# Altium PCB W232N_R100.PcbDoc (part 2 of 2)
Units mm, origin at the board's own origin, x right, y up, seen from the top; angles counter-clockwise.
Board outline 70 x 46.25 mm, 4 copper layers (Top Layer, Layer 1, Layer 2, Bottom Layer), stack 1.584 mm thick; 133 components, 105 nets, 435 pads, 346 vias.
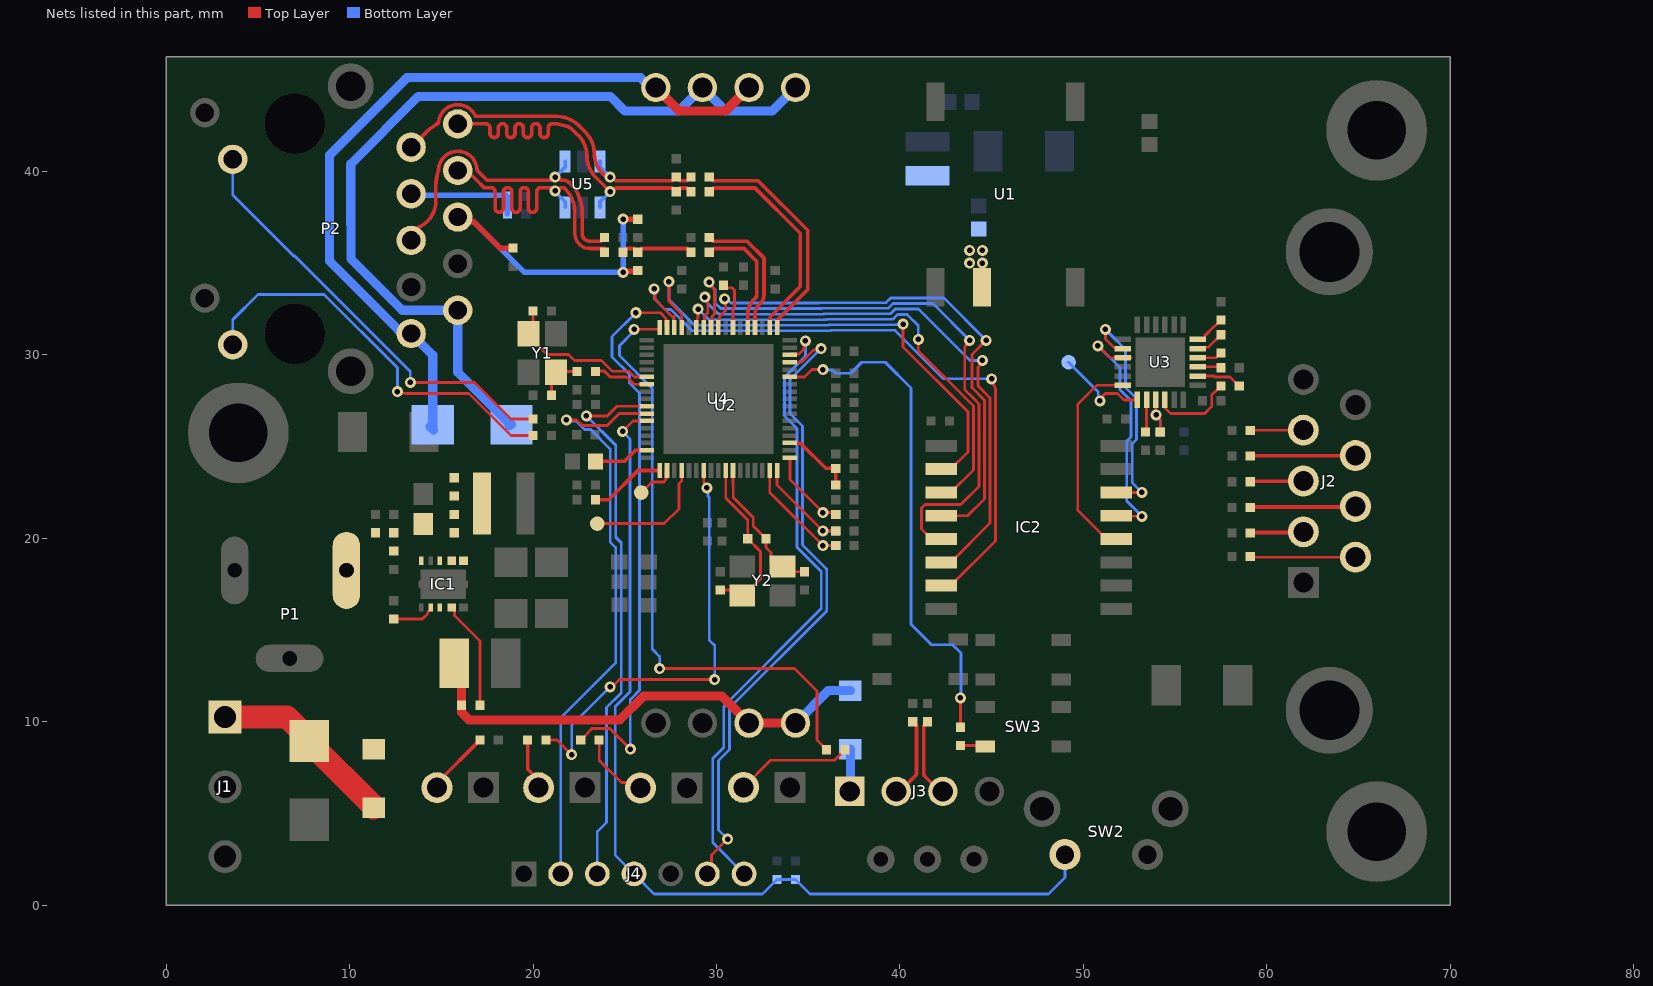
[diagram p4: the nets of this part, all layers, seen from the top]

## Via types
v1: diameter 0.6, hole 0.3, Top Layer to Bottom Layer, tented both sides, 346 vias

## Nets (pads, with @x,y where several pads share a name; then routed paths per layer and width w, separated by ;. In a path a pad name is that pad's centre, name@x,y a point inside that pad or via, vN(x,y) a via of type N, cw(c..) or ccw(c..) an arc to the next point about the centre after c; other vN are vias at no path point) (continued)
MDI_R1_P: C20.1 R34.2 R37.2 | length 4
  Top Layer w0.2: C20.1@24.9,35.6 25.1,35.8 25.5,35.8 R37.2@25.7,35.6 25.9,35.8 28.4,35.8 R34.2@28.6,35.6
MDI_R_N: C23.2 P2.R6 U5.4 | length 18.7
  Top Layer w0.2: P2.R6@13.35,36.247 13.35,36.69 cw(c13.55,36.689) 13.504,36.883 ccw(c13.151,38.388) 14.696,38.388 14.696,39.181 cw(c17.412,39.19) 14.831,40.034 ccw(c14.641,40.096) 14.84,40.089 cw(c15.89,40.057) 16.937,40.142 ccw(c17.136,40.16) 16.993,40.02 17.09,39.923 17.488,39.525 20.917,39.525 21.092,39.7 v1(21.2,39.7) cw(c21.2,39.439) 21.385,39.623 ccw(c21.622,39.861) 21.622,39.525 cw(c21.622,38.979) 22.008,39.365 22.039,39.334 ; 22.039,39.334 cw(c20.506,37.802) 22.674,37.802 22.674,36.626 ccw(c23.1,36.626) 23.1,36.2 23.7,36.2 C23.2@23.9,36.4
  Bottom Layer w0.2: v1(21.2,39.7) 21.75,40.25 U5.4@21.75,40.55
MDI_R_P: C20.2 P2.R3 U5.3 | length 18.8
  Top Layer w0.2: P2.R3@16.218,40.23 16.918,39.53 17.323,39.125 17.699,39.125 cw(c17.699,38.898) 17.926,38.898 17.926,38.005 ccw(c18.153,38.005) 18.38,38.005 18.38,38.898 cw(c18.607,38.898) 18.834,38.898 18.834,38.005 ccw(c19.061,38.005) 19.288,38.005 19.288,38.898 cw(c19.515,38.898) 19.742,38.898 19.742,38.005 ccw(c19.969,38.005) 20.196,38.005 20.196,38.898 cw(c20.423,38.898) 20.423,39.125 20.917,39.125 21.092,38.95 21.1,38.95 v1(21.2,38.95) ccw(c21.2,39.211) 21.385,39.027 21.413,39.054 cw(c21.583,38.884) 21.583,39.125 cw(c21.583,38.884) 21.753,39.054 cw(c20.497,37.798) 22.274,37.798 22.274,36.626 ccw(c23.1,36.626) 22.274,36.607 ccw(c23.1,36.626) 23.081,35.8 ccw(c23.1,36.626) 23.1,35.8 C20.2@23.866,35.8
  Bottom Layer w0.2: v1(21.2,38.95) 21.2,38.9 21.75,38.35 U5.3@21.75,38.05
MDI_T_N: P2.R2 R27.1 R31.2 U5.6 | length 20.6
  Top Layer w0.2: P2.R2@13.35,41.327 14.179,42.156 cw(c15.975,40.36) 14.748,42.584 ccw(c14.65,42.759) 14.849,42.732 cw(c15.89,42.597) 15.147,43.339 ; 15.148,43.34 cw(c15.89,42.597) 15.89,43.647 cw(c15.89,42.597) 16.852,43.019 ccw(c16.878,43.045) 16.878,43.008 21.275,43.008 cw(c21.275,41.277) 22.499,42.501 22.857,42.143 cw(c21.699,40.986) 23.336,40.986 ccw(c24.92,40.986) 23.8,39.866 ccw(c24.015,40.081) 24.015,39.777 cw(c24.015,39.515) v1(24.2,39.7) 24.308,39.7 24.508,39.5 26.2,39.5 27.2,39.5 27.6,39.5 R27.1@27.8,39.7 28,39.5 28.4,39.5 R31.2@28.6,39.7
  Bottom Layer w0.2: P2.R2@13.35,41.327 ccw(c13.35,42.114) 13.907,41.558 P2.R2@13.983,41.634 ; U5.6@23.65,40.55 23.65,40.25 v1(24.2,39.7)
MDI_T_P: P2.R1 R26.1 R32.2 U5.1 | length 20.7
  Top Layer w0.2: P2.R1@15.89,42.597 cw(c15.916,42.571) 15.916,42.608 15.958,42.608 17.42,42.608 cw(c17.42,42.381) 17.647,42.381 17.647,42.079 ccw(c17.874,42.079) 18.101,42.079 18.101,42.381 cw(c18.328,42.381) 18.555,42.381 18.555,42.079 ccw(c18.782,42.079) 19.009,42.079 19.009,42.381 cw(c19.236,42.381) 19.463,42.381 19.463,42.079 ccw(c19.69,42.079) 19.917,42.079 19.917,42.381 cw(c20.144,42.381) 20.371,42.381 20.371,42.079 ccw(c20.598,42.079) 20.825,42.079 20.825,42.381 cw(c21.052,42.381) 21.052,42.608 21.274,42.608 21.893,42.456 cw(c21.274,41.274) 21.993,42.398 cw(c21.274,41.274) 22.217,42.217 22.464,41.97 cw(c21.325,40.831) 22.936,40.831 ccw(c24.547,40.831) 23.408,39.692 23.6,39.5 v1(24.2,38.9) 24.308,38.9 24.508,39.1 26.366,39.1 27.034,39.1 27.6,39.1 R26.1@27.8,38.9 28,39.1 28.4,39.1 R32.2@28.6,38.9
  Bottom Layer w0.2: U5.1@23.65,38.05 23.65,38.35 v1(24.2,38.9)
NetC1_1: C1.1 R1.1
NetC1_2: C1.2 IC1.2
NetC2_1: C2.1 IC1.5 R4.1 R6.2
NetC6_2: C6.2 IC1.3
NetC9_2: C9.2 L2.2 U1.2
  other v1: 43.8,35 44.5,35 43.8,35.7 44.5,35.7
NetC13_1: C13.1 U3.21 | length 1.3
  Top Layer w0.152: U3.21@56.25,29.35 57.45,29.35 C13.1@57.5,29.3
NetC13_2: C13.2 U3.16 | length 4.6
  Top Layer w0.152: U3.16@54.45,27.55 54.45,27.1 54.75,26.8 56.62,26.8 57,27.18 57,27.82 57.156,27.976 57.176,27.976 C13.2@57.5,28.3
NetC14_2: C14.2 U3.20 | length 2.5
  Top Layer w0.152: U3.20@56.25,28.85 57.13,28.85 57.18,28.8 58,28.8 C14.2@58.5,28.3
NetC15_1: C15.1 U3.22 | length 1.4
  Top Layer w0.152: U3.22@56.25,29.85 57.25,29.85 C15.1@57.5,30.1
NetC15_2: C15.2 U3.23 | length 1.6
  Top Layer w0.152: U3.23@56.25,30.35 56.324,30.424 56.824,30.424 C15.2@57.5,31.1
NetC16_2: C16.2 U3.24 | length 1.8
  Top Layer w0.152: U3.24@56.25,30.85 56.55,30.85 56.624,30.924 56.624,31.044 57.156,31.576 57.176,31.576 C16.2@57.5,31.9
NetC22_2: C22.2 R21.1 U4.54 | length 4
  Top Layer w0.2: U4.54@34,25.2 34.025,25.175 34.599,25.175 35.95,23.824 36.476,23.824 C22.2@36.5,23.8 R21.1@36.5,22.9
NetC26_2: C26.2 U4.35 | length 4.2
  Top Layer w0.2: C26.2@23.4,22.1 24.12,22.1 25.72,23.7 U4.35@26.9,23.7
NetC27_2: C27.2 U4.33 | length 3.3
  Top Layer w0.2: C27.2@23.4,24.2 24.979,24.2 25.579,24.8 U4.33@26.2,24.8
  Top Layer w0.3: C27.2@23.4,24.2 C27.2@23.554,24.046
NetC50_2: C50.2 R39.1 Y1.1 | length 2.5
  Top Layer w0.152: C50.2@21,27.8 21,28.8 Y1.1@21.25,29.05 21.3,29.1 R39.1@22.4,29.1
NetD2_2: D2.2 D3.2 J1.1 P1.1 | length 11
  Top Layer w1: J1.1@3.2,10.26 J1.1@3.6,9.86
  Top Layer w1.27: J1.1@3.2,10.26 6.565,10.26 7.8,9.025 D3.2@7.8,8.95 7.8,8.875 11.3,5.375 D2.2@11.3,5.3
  Bottom Layer w1: J1.1@3.2,10.26 J1.1@3.295,10.355
NetD4_2: D4.2 R5.1 | length 3.5
  Top Layer w0.2: D4.2@14.8,6.5 14.8,6.7 R5.1@17.1,9
NetD6_2: D6.2 R40.1 | length 4
  Top Layer w0.152: R40.1@23.6,9 23.6,7.9 24.819,6.681 25.619,6.681 D6.2@25.9,6.4
NetD7_2: D7.2 R43.1 | length 6.4
  Top Layer w0.152: D7.2@31.467,6.422 32.945,7.9 36.429,7.9 R43.1@37,8.471
NetD8_2: D8.2 R44.1 | length 3
  Top Layer w0.2: R44.1@19.7,9 19.7,7.403 20.3,6.803 D8.2@20.3,6.5 ; D8.2@20.3,6.4 D8.2@20.3,6.5 ; D8.2@20.4,6.4 D8.2@20.3,6.5
NetIC1_1: IC1.1 L1.1 R1.2
NetIC1_7: IC1.7 R3.2 | length 2.4
  Top Layer w0.152: R3.2@12.4,15.6 13.951,15.6 14.257,15.906 14.257,15.976 14.406,16.125 IC1.7@14.406,16.225
NetIC1_9: IC1.9 R2.2 | length 6
  Top Layer w0.152: IC1.9@15.556,16.225 15.569,16.225 15.717,16.076 15.717,15.783 17.1,14.4 R2.2@17.1,10.9
NetIC2_2: IC2.2 U4.14 | length 27.4
  Top Layer w0.152: v1(27.4,34) 27.408,33.992 27.408,32.93 28.1,32.239 U4.14@28.1,31.5 ; v1(40.175,31.675) 40.175,30.432 43.707,26.9 43.707,24.702 42.775,23.77 IC2.2@42.25,23.77
  Bottom Layer w0.152: v1(27.4,34) 27.408,33.992 27.408,33.008 28.795,31.621 36.1,31.621 36.124,31.645 40.145,31.645 v1(40.175,31.675)
NetIC2_3: IC2.3 U4.12 | length 24.9
  Top Layer w0.15: U4.12@28.95,31.65 28.95,31.993 28.994,32.037 v1(28.994,32.502)
  Top Layer w0.152: v1(41,30.85) 41,30.215 44.009,27.206 44.009,23.734 42.775,22.5 IC2.3@42.25,22.5
  Bottom Layer w0.15: v1(28.994,32.502) 29.573,31.923 35.975,31.923 35.999,31.946 39.617,31.946 39.871,32.2 40.394,32.2 41,31.594 v1(41,30.85)
NetIC2_4: IC2.4 U4.9 | length 29.1
  Top Layer w0.152: U4.9@30.1,31.5 30.149,31.549 30.149,32.074 30.5,32.425 30.5,32.998 v1(30.448,33.05) ; IC2.4@42.25,21.23 43.691,21.23 44.614,22.153 44.614,27.531 44.559,27.586 43.929,28.215 43.929,30.029 v1(44.7,30.8)
  Bottom Layer w0.152: v1(30.448,33.05) 30.569,33.05 30.793,32.826 35.601,32.826 35.625,32.85 39.243,32.85 39.5,33.106 40.697,33.106 40.703,33.1 42.4,33.1 v1(44.7,30.8)
NetIC2_5: IC2.5 U4.10 | length 33.4
  Top Layer w0.15: v1(29.6,33.975) 29.6,33.853 29.889,33.565 29.889,32.227 29.75,32.089 29.75,31.55 U4.10@29.7,31.5 ; v1(43.8,30.8) 43.8,30.714 43.531,30.445 43.531,28.112 43.971,27.671
  Top Layer w0.152: IC2.5@42.25,19.96 41.725,19.96 41.174,20.511 41.174,21.649 41.375,21.85 43.265,21.85 ccw(c43.265,22.002) 43.373,21.895 44.312,22.834 44.312,27.331 43.971,27.671
  Bottom Layer w0.15: v1(29.6,33.975) 29.6,33.878 29.923,33.555 29.923,32.833 30.23,32.525 35.726,32.525 35.749,32.548 39.368,32.548 39.624,32.805 40.573,32.805 40.579,32.799 41.801,32.799 v1(43.8,30.8)
NetIC2_6: IC2.6 U4.11 | length 31.2
  Top Layer w0.152: U4.11@29.3,31.5 29.349,31.549 29.349,32.113 29.52,32.284 29.52,32.877 ; IC2.6@42.25,18.69 42.775,18.69 44.916,20.831 44.916,27.656 44.25,28.322 44.25,29.329 44.5,29.579 v1(44.5,29.7)
  Bottom Layer w0.152: v1(29.364,33.155) 29.364,33.034 29.52,32.877 29.52,32.809 29.564,32.765 29.84,32.489 ; 29.841,32.489 30.016,32.313 ccw(c30.23,32.525) 30.226,32.224 35.851,32.224 35.874,32.247 39.493,32.247 39.747,32.501 40.45,32.501 40.454,32.498 41.017,32.498 43.814,29.7 v1(44.5,29.7)
NetIC2_7: IC2.7 U4.15 | length 36.8
  Top Layer w0.152: v1(26.6,33.6) 26.649,33.551 26.649,33.024 27.651,32.021 27.651,31.549 U4.15@27.7,31.5 27.7,32.112 ; IC2.7@42.25,17.42 42.775,17.42 45.219,19.864 45.219,28.112 ccw(c45.066,28.112) 45.208,28.169 v1(44.995,28.7)
  Bottom Layer w0.152: v1(26.6,33.6) 26.601,33.599 26.601,33.071 27.19,32.482 27.507,32.482 27.682,32.307 28.67,31.319 36.225,31.319 36.249,31.342 39.725,31.342 40.716,30.352 42.367,28.7 v1(44.995,28.7)
NetJ2_2: J2.2 R8.2 | length 2.9
  Top Layer w0.2: R8.2@59.1,20.281 59.137,20.318 61.963,20.318 J2.2@62,20.355
NetJ2_3: J2.3 R10.2 | length 2.9
  Top Layer w0.2: R10.2@59.1,23.081 59.122,23.103 61.978,23.103 J2.3@62,23.125
NetJ2_4: J2.4 R12.2 | length 2.9
  Top Layer w0.152: R12.2@59.1,25.881 59.114,25.895 J2.4@62,25.895
NetJ2_6: J2.6 R7.2 | length 5.8
  Top Layer w0.152: R7.2@59.1,19 59.13,18.97 J2.6@64.84,18.97
NetJ2_7: J2.7 R9.2 | length 5.8
  Top Layer w0.2: R9.2@59.1,21.681 59.13,21.711 64.811,21.711 J2.7@64.84,21.74
NetJ2_8: J2.8 R11.2 | length 5.8
  Top Layer w0.2: R11.2@59.1,24.481 59.114,24.496 64.825,24.496 J2.8@64.84,24.51
NetJ3_2: J3.2 R17.1 | length 4.2
  Top Layer w0.2: J3.2@40,6.2 40.842,7.042 ccw(c40.7,7.183) 40.9,7.183 40.9,9.717 ccw(c40.7,9.717) 40.841,9.859 R17.1@40.7,10
NetJ3_3: J3.3 R16.1 | length 4.4
  Top Layer w0.2: R16.1@41.5,10 41.359,9.859 ccw(c41.5,9.717) 41.3,9.717 41.3,7.165 ccw(c41.5,7.167) 41.358,7.026 42.126,6.258 ccw(c42.267,6.4) 42.267,6.2 J3.3@42.34,6.2
NetP2_L1: P2.L1 R19.1 | length 22.4
  Top Layer w0.152: v1(12.6,28) 12.686,27.914 13.086,27.914 13.1,27.9 16.5,27.9 18.8,25.6 R19.1@20,25.6 R19.1@20.1,25.6
  Bottom Layer w0.152: P2.L1@3.62,30.557 3.62,31.92 5,33.3 8.6,33.3 12.6,29.3 v1(12.6,28)
NetP2_L3: P2.L3 R20.1 | length 23.7
  Top Layer w0.152: v1(13.3,28.5) 16.8,28.5 18.8,26.5 R20.1@20,26.5
  Bottom Layer w0.152: P2.L3@3.62,40.667 3.62,38.725 6.945,35.4 7,35.4 13.3,29.1 v1(13.3,28.5)
NetR13_2: R13.2 U3.14 | length 1.8
  Top Layer w0.152: R13.2@53.4,25.8 53.45,25.85 U3.14@53.45,27.55
NetR14_2: R14.2 R15.2 U3.15 | length 2.5
  Top Layer w0.152: v1@53.95,26.737 U3.15@53.95,27.55 ; R14.2@54.2,25.8 54.2,26.487
  Bottom Layer w0.152: v1(53.976,26.737) 53.976,26.616 54.2,26.392 R15.2@54.2,25.8
NetR22_1: R22.1 R28.2 U4.52 | length 5.1
  Top Layer w0.152: U4.52@34,24.4 34,23.2 v1(35.8,21.4) 36.326,21.4 36.4,21.326 R22.1@36.4,21.3
  Bottom Layer w0.152: v1(35.8,21.4) 36.4,21.4 R28.2@36.5,21.3
NetR23_1: R23.1 R29.2 U4.51 | length 5.7
  Top Layer w0.152: U4.51@33.3,23.7 33.3,22.9 v1(35.8,20.4) R23.1@36.5,20.4
  Bottom Layer w0.152: v1(35.8,20.4) R29.2@36.5,20.4
NetR24_1: R24.1 R30.2 U4.50 | length 6.4
  Top Layer w0.152: U4.50@32.9,23.7 32.9,22.5 v1(35.8,19.6) ; 36.1,19.6 R24.1@36.5,19.6
  Bottom Layer w0.152: v1(35.8,19.6) R30.2@36.5,19.6
NetR25_1: R25.1 U4.63 | length 28
  Top Layer w0.152: U4.63@34,28.8 34.801,28.8 35.201,29.2 v1(35.8,29.2) ; R25.1@43.3,9.7 v1(43.3,11.3)
  Bottom Layer w0.152: v1(35.8,29.2) 35.829,29.171 36.329,29.171 36.5,29 37.318,29 37.918,29.6 39.2,29.6 40.598,28.202 40.598,15.314 41.714,14.198 42.875,14.198 43.326,13.746 43.326,11.326 v1(43.3,11.3)
NetR25_2: R25.2 SW3.3 | length 1.4
  Top Layer w0.15: R25.2@43.25,8.75 R25.2@43.3,8.7 SW3.3@44.6,8.7
NetR35_2: R35.2 U4.7 | length 2.8
  Top Layer w0.152: R35.2@30.375,33.8 30.512,33.663 30.837,33.663 30.974,33.526 30.974,32.624 30.9,32.551 U4.7@30.9,31.5
NetTP1_1: TP1.1 U3.13 | length 5.2
  Top Layer w0.152: v1(50.9,27.5) 50.9,27.6 51.2,27.9 51.863,27.9 52.213,27.55 U3.13@52.95,27.55
  Bottom Layer w0.152: TP1.1@49.2,29.6 50.814,27.986 50.814,27.586 v1(50.9,27.5)
NetTP2_1: TP2.1 U4.38 | length 6.8
  Top Layer w0.152: TP2.1@23.6,20.8 27.144,20.8 27.946,21.602 27.946,22.975 28.1,23.129 U4.38@28.1,23.7
NetTP3_1: TP3.1 U4.36 | length 2.2
  Top Layer w0.152: TP3.1@25.893,22.495 26.472,23.074 27.119,23.074 27.251,23.206 27.251,23.651 U4.36@27.3,23.7
POE+: D5.2 P2.R9 U2.1 U2.3 | length 47.5
  Bottom Layer w0.5: P2.R9@15.877,32.424 15.863,32.437 12.863,32.437 10.059,35.241 10.059,37.091 10.05,37.1 10.05,40.406 13.744,44.1 24.2,44.1 25,43.3 27.949,43.3 U2.3@29.23,44.581 30.511,43.3 33.029,43.3 U2.1@34.31,44.581 ; P2.R9@15.89,32.437 15.89,29.06 D5.2@18.675,26.275 ; D5.2@18.675,26.125 D5.2@18.675,26.275 ; D5.2@18.825,26.2 18.75,26.2 D5.2@18.675,26.275
POE-: D5.1 P2.R10 U2.2 U2.4 | length 43.6
  Top Layer w0.5: U2.4@26.69,44.581 27.971,43.3 30.489,43.3 U2.2@31.77,44.581
  Bottom Layer w0.5: D5.1@14.375,26.1 D5.1@14.575,25.9 ; D5.1@14.525,26 D5.1@14.525,26.125 ; D5.1@14.525,26.2 14.525,29.992 13.14,31.377 12.637,31.377 8.9,35.115 8.9,40.9 13.122,45.122 25.851,45.122 26.392,44.581 U2.4@26.69,44.581
POE_OUT: C3.2 D1.1 D2.1 IC1.8 R2.1 U2.7 U2.8 | length 26.1
  Top Layer w0.5: C3.2@15.7,13.2 16.1,12.8 R2.1@16.1,10.9 16.1,10.5 16.5,10.1 24.725,10.1 26.025,11.4 30.291,11.4 U2.7@31.77,9.921 U2.8@34.31,9.921
  Bottom Layer w0.5: U2.8@34.31,9.921 36.089,11.7 D1.1@37.3,11.7
R_N: R33.1 U4.4 | length 7.4
  Top Layer w0.2: R33.1@29.6,36.4 29.8,36.2 31.666,36.2 32.586,35.28 32.586,33.25 cw(c31.986,33.25) 32.411,32.827 32.304,32.72 ccw(c32.8,32.226) 32.1,32.226 32.1,31.781 cw(c31.7,31.781) 32.1,31.779 cw(c31.9,31.777) 32.1,31.777 U4.4@32.1,31.5
R_P: R34.1 U4.5 | length 6.7
  Top Layer w0.2: R34.1@29.6,35.6 29.718,35.718 cw(c29.916,35.519) 29.916,35.8 31.5,35.8 32.186,35.114 32.186,33.25 cw(c31.986,33.25) 32.128,33.109 32.022,33.003 ccw(c32.8,32.226) 31.7,32.226 31.7,31.776 31.7,31.77 ccw(c33.131,31.767) U4.5@31.7,31.765 ; U4.5@31.7,31.5 U4.5@31.7,31.764
RCT: C25.2 P2.R5 R36.1 R37.1 | length 18.9
  Top Layer w0.3: P2.R5@15.89,37.517 16.139,37.268 16.757,37.268 18.2,35.825 C25.2@18.9,35.825 ; v1(24.9,34.5) 24.95,34.55 25.65,34.55 R37.1@25.7,34.6 ; v1(24.9,37.4) R36.1@25.7,37.4
  Bottom Layer w0.3: v1(24.9,37.4) v1(24.9,34.5) 19.525,34.5 16.757,37.268 P2.R5@16.173,37.268 ; P2.R5@16.173,37.268 15.924,37.517 P2.R5@15.89,37.517 16.139,37.268 P2.R5@16.173,37.268
RSTn: C28.2 J4.4 R38.1 SW2.1 U4.29 | length 53.1
  Top Layer w0.152: v1(24.875,25.825) 25.45,26.4 25.876,26.4 25.898,26.378 25.898,26.351 26.151,26.351 U4.29@26.2,26.4 ; SW2.1@49,2.75 49.05,2.75 SW2.1@49.1,2.8
  Bottom Layer w0.152: v1(24.875,25.825) 25.288,25.412 25.288,11.633 24.474,10.818 24.474,2.726 J4.4@25.5,1.7 ; J4.4@25.6,1.8 25.6,1.6 26.6,0.6 32.5,0.6 R38.1@33.3,1.4 C28.2@34.3,1.4 35.1,0.6 48.1,0.6 49,1.5 SW2.1@49,2.75
RTS: IC2.14 U3.8 | length 13.5
  Top Layer w0.152: v1(51.2,31.4) 51.209,31.391 51.209,30.871 51.656,30.424 52.076,30.424 U3.8@52.15,30.35 ; IC2.14@51.275,22.5 IC2.14@51.8,22.5 v1(53.2,22.5)
  Bottom Layer w0.152: v1(51.2,31.4) 52.298,30.302 52.298,28.225 52.898,27.625 52.898,25.394 52.674,25.17 52.674,23.026 v1(53.2,22.5)
RX: IC2.12 U3.12 | length 11.4
  Top Layer w0.152: IC2.12@51.8,19.96 51.275,19.96 49.693,21.542 49.693,27.293 50.75,28.35 U3.12@52.15,28.35
STATUS_LED0: R40.2 U4.16 | length 30.9
  Top Layer w0.152: R40.2@22.576,8.976 R40.2@22.6,9 22.989,9.389 22.989,9.413 23.2,9.624 24.176,9.624 v1(25.3,8.5) ; v1(25.6,32.3) 26.945,32.3 27.251,31.994 27.251,31.549 U4.16@27.3,31.5
  Bottom Layer w0.152: v1(25.3,8.5) 25.3,11.217 25.8,11.717 25.8,27.919 25.248,28.472 25.248,28.948 24.3,29.895 24.3,31 v1(25.6,32.3)
STATUS_LED1: R43.2 U4.17 | length 34
  Top Layer w0.152: v1(25.5,31.4) 26.851,31.4 26.9,31.449 U4.17@26.9,31.5 U4.17@26.9,31.775 ; v1(26.9,12.9) 34.245,12.9 35.479,11.666 35.479,10.334 35.474,10.329 35.474,8.997 R43.2@36,8.471
  Bottom Layer w0.152: v1(25.5,31.4) 25.5,31.297 24.702,30.499 24.702,30.064 24.704,30.061 24.704,29.963 26.498,28.169 26.498,13.958 26.9,13.556 v1(26.9,12.9)
STATUS_LED2: R44.2 U4.41 | length 24.2
  Top Layer w0.152: R44.2@20.7,9 21.3,9 v1(22.1,8.2) ; v1(24.2,11.9) 24.3,11.9 24.7,12.3 v1(29.9,12.3) v1@30,12.2 ; U4.41@29.3,23.7 29.3,23.046 29.475,22.871 v1(29.475,22.75)
  Top Layer w0.2: R44.2@20.7,9 R44.2@20.85,8.85
  Bottom Layer w0.152: v1(22.1,8.2) 22.1,9.8 v1(24.2,11.9) ; v1(29.475,22.75) 29.537,22.688 29.537,22.277 29.6,22.214 29.6,14.508 ccw(c29.752,14.508) 29.645,14.401 29.9,14.145 v1(29.9,12.3)
SWCLK: J4.3 U4.27 | length 32.1
  Top Layer w0.152: v1(22.9,26.676) 24.04,26.676 24.564,27.2 U4.27@26.2,27.2
  Bottom Layer w0.152: J4.3@23.5,1.7 23.5,4.012 24,4.512 24,10.772 24.802,11.575 24.802,19.755 24.502,20.055 24.502,25.073 v1(22.9,26.676) 24.458,25.117 cw(c24.35,25.01) 24.47,25.104 cw(c24.35,25.01) 24.502,25.012
SWDIO: J4.2 U4.28 | length 32.5
  Top Layer w0.152: v1(21.809,26.458) 22.37,26.458 22.678,26.15 24.043,26.15 24.694,26.8 U4.28@26.2,26.8
  Bottom Layer w0.152: J4.2@21.5,1.6 21.5,10.2 24.5,13.2 24.5,19.5 24.2,19.8 24.2,24.869 23.141,25.929 22.8,25.929 22.338,26.391 21.876,26.391 v1(21.809,26.458)
T_N: R31.1 U4.1 | length 12.6
  Top Layer w0.2: R31.1@29.6,39.7 29.8,39.5 32.266,39.5 34.969,36.797 34.969,33.564 33.325,31.921 33.325,31.525 U4.1@33.3,31.5
T_P: R32.1 U4.2 | length 11.9
  Top Layer w0.2: R32.1@29.6,38.9 29.8,39.1 32.1,39.1 34.569,36.631 34.569,33.73 32.925,32.086 32.925,31.525 U4.2@32.9,31.5
TCT: C21.2 P2.R4 R18.1 | length 6.3
  Bottom Layer w0.3: P2.R4@13.35,38.787 13.418,38.719 18.532,38.719 C21.2@18.6,38.65 R18.1@18.6,37.7
TX: IC2.13 U3.9 | length 14.5
  Top Layer w0.152: v1(50.8,30.5) 51.45,29.85 U3.9@52.15,29.85 52.6,29.85 ; IC2.13@51.275,21.23 IC2.13@51.8,21.23 51.83,21.2 v1(53.2,21.2)
  Bottom Layer w0.152: v1(50.8,30.5) 51.995,29.305 51.995,28.099 52.595,27.499 52.595,25.519 52.371,25.295 52.371,22.029 v1(53.2,21.2)
U_RXD0: J4.7 U4.66 | length 34.9
  Top Layer w0.152: U4.66@34,30 34.049,30.049 34.494,30.049 34.764,30.319 34.764,30.676 v1(34.85,30.762)
  Bottom Layer w0.152: J4.7@31.5,1.7 29.798,3.402 29.798,8.006 30.398,8.606 30.398,10.728 cw(c30.7,10.728) 30.486,10.942 35.71,16.166 35.71,18.19 34.386,19.514 34.386,25.992 33.704,26.675 33.704,28.781 34.85,29.928 v1(34.85,30.762)
U_TXD0: J4.6 U4.65 | length 35.3
  Top Layer w0.152: J4.6@29.496,1.704 J4.6@29.5,1.7 29.725,1.925 29.725,2.725 v1(30.6,3.6) ; U4.65@34,29.6 34.629,29.6 35.293,30.264 35.614,30.264 v1(35.7,30.35)
  Bottom Layer w0.152: J4.6@29.5,1.7 J4.6@29.5,1.7 ; v1(30.6,3.6) 30.1,4.1 30.1,7.881 30.7,8.481 30.7,10.666 cw(c30.852,10.665) 30.744,10.772 36.012,16.04 36.012,18.316 35.913,18.415 34.689,19.639 34.689,26.118 34.006,26.8 34.006,28.656 v1(35.7,30.35)
USB_5V: D1.2 J3.1 | length 2.2
  Bottom Layer w0.5: J3.1@37.3,6.3 D1.2@37.3,8.5
XIN: C51.2 U4.23 Y1.3 | length 8.8
  Top Layer w0.152: Y1.3@19.75,30.75 Y1.3@19.75,30.85 ; Y1.3@19.75,31.05 20.424,30.376 20.424,30.356 20.752,30.028 21.93,30.028 22.258,29.7 23.734,29.7 24.328,29.106 25.222,29.106 25.528,28.8 U4.23@26.2,28.8 ; Y1.3@19.8,30.9 19.75,30.95 19.75,31.05 20,31.3 20,32.1
XOUT: R39.2 U4.24 | length 3.2
  Top Layer w0.152: R39.2@23.4,29.2 R39.2@23.4,29.1 23.43,29.13 23.876,29.13 24.203,28.804 25.096,28.804 25.274,28.626 25.274,28.616 25.49,28.4 U4.24@26.2,28.4
XTAL1: C52.2 R42.1 U4.45 Y2.1 | length 7.6
  Top Layer w0.152: U4.45@30.9,23.7 30.9,22.91 ; Y2.1@33.1,18.476 32.976,18.6 32.976,19.221 32.7,19.497 R42.1@32.7,19.976 32.002,20.673 32.002,21.125 30.91,22.217 30.91,22.89 ; Y2.1@33.5,18.476 33.8,18.176 C52.2@34.8,18.176 ; 30.9,22.91 30.9,22.9 30.91,22.89 ; 30.9,22.91 30.91,22.899 30.91,22.89
XTAL2: C53.2 R42.2 U4.44 Y2.3 | length 9.4
  Top Layer w0.152: C53.2@30.2,17.176 31.1,17.176 Y2.3@31.4,16.876 31.5,16.876 32.4,17.776 32.4,19.276 32.3,19.376 31.8,19.876 R42.2@31.8,19.976 ; U4.44@30.5,23.7 30.5,22.2 31.7,21 R42.2@31.7,19.976
pads on no net: IC1.4 J2.1 J2.9 P2.0 P2.R8 SW1.2 SW3.2 SW3.4 SW4.1 SW5.2 SW5.4 U1.8 U4.18 U4.19 U4.30 U4.32 U4.46 U4.47 U4.48 U4.49 U4.67 U4.68

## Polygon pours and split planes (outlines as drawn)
GND on Bottom Layer "NONET_L-01_P-001" (solid, remove dead copper, pour order 0): 46.171,45.7 46.171,32.379 46.2,32.35 43.451,29.601 43.451,11.752 46.352,8.85 55.8,8.85 55.8,8.75 58.6,5.95 58.597,0.5 0,0.5 0,27.704 17.854,27.704 17.9,27.75 17.859,27.791 17.859,45.7
GND_1 on Bottom Layer "NONET_L-01_P-001" (solid, pour order 2): 47.81,45.7 47.81,33.26 45.7,31.15 45.7,11.45 46.9,10.25 59.8,10.25 59.8,16.125 65.8,16.125 65.8,30.125 59.1,30.125 59.1,45.7
GND on Top Layer "NONET_L-01_P-001" (solid, remove dead copper, pour order 1): 46.171,45.7 46.171,32.379 46.2,32.35 43.451,29.601 43.451,11.752 46.352,8.85 55.8,8.85 55.8,8.75 58.6,5.95 58.597,0.5 0,0.5 0,27.704 17.854,27.704 17.9,27.75 17.859,27.791 17.859,45.7
GND_1 on Top Layer "NONET_L-01_P-001" (solid, pour order 3): 47.81,45.7 47.81,33.26 45.7,31.15 45.7,11.45 46.9,10.25 59.8,10.25 59.8,16.125 65.8,16.125 65.8,30.125 59.1,30.125 59.1,45.7
3.3V_1 on Layer 2 (split plane): 59.499,13.75 56.5,13.75 56.5,10.55 47.999,10.55 48.001,45.74 59.501,45.74
3.3V on Layer 2 (split plane): 45.443,32.75 45.443,7.95 55.243,7.95 57.443,5.75 57.425,5.732 57.425,0.51 13.273,0.51 12.701,1.082 12.701,20.45 12.701,22.4 12.696,22.439 12.681,22.476 12.657,22.507 12.626,22.531 12.589,22.546 12.55,22.551 12.38,22.551 12.38,23.794 20.324,23.794 20.324,19.9 20.329,19.871 20.346,19.846 20.413,19.779 20.426,19.77 20.438,19.762 20.467,19.756 25.749,19.756 25.749,19.475 25.755,19.445 25.771,19.421 25.774,19.418 25.774,17.35 25.779,17.321 25.796,17.296 25.846,17.246 25.861,17.236 25.871,17.229 25.9,17.224 28.811,17.224 28.84,17.229 28.865,17.246 28.882,17.271 28.887,17.3 28.887,19.251 28.887,19.731 28.882,19.76 28.865,19.785 28.84,19.802 28.811,19.808 28.151,19.808 28.151,23.85 28.146,23.879 28.129,23.904 27.879,24.154 27.854,24.171 27.825,24.176 24.276,24.176 24.276,35.124 29.789,35.124 29.824,35.088 29.824,33.3 29.83,33.271 29.847,33.246 29.871,33.229 29.901,33.224 35.762,33.224 35.791,33.229 35.816,33.246 35.832,33.271 35.838,33.3 35.838,45.74 45.443,45.74
3V3A on Layer 2 (split plane): 25.238,42.785 35.685,42.785 35.685,33.376 29.977,33.376 29.977,35.12 29.971,35.149 29.955,35.174 29.875,35.254 29.85,35.271 29.821,35.276 24.2,35.276 24.171,35.271 24.146,35.254 24.129,35.229 24.124,35.2 24.124,24.1 24.129,24.071 24.146,24.046 24.171,24.029 24.2,24.024 27.793,24.024 27.999,23.818 27.999,19.731 28.004,19.702 28.021,19.677 28.046,19.66 28.075,19.655 28.734,19.655 28.734,19.251 28.734,17.376 25.932,17.376 25.926,17.382 25.926,19.45 25.921,19.479 25.904,19.504 25.902,19.506 25.902,19.833 25.896,19.862 25.879,19.887 25.855,19.903 25.825,19.909 20.499,19.909 20.476,19.932 20.476,23.9 20.471,23.929 20.454,23.954 20.429,23.971 20.4,23.976 20.371,23.971 20.346,23.954 20.341,23.946 12.38,23.946 12.38,27.77 17.812,27.77 17.812,27.839 17.827,27.829 17.856,27.824 17.885,27.829 17.91,27.846 17.923,27.859 17.94,27.884 17.946,27.913 17.946,43.5 17.94,43.529 17.923,43.554 17.898,43.571 17.875,43.575 17.875,45.74 25.238,45.74
NetD2_2 on Layer 2 (split plane): 10.524,22.269 10.561,22.254 10.6,22.249 12.399,22.249 12.399,20.45 12.399,1.082 11.827,0.51 5.044,0.51 5.044,3.184 2.3,5.8 2.3,9.197 2.287,9.21 2.287,11.31 2.97,11.993 2.97,22.27 10.523,22.27
GND_1 on Layer 1 (split plane): 59.498,30.875 59.507,30.757 59.535,30.643 59.58,30.533 59.641,30.433 59.718,30.343 59.808,30.266 59.908,30.205 60.018,30.16 60.132,30.132 60.25,30.123 63.748,30.123 63.748,26.952 60.25,26.952 60.132,26.943 60.018,26.915 59.908,26.87 59.808,26.809 59.718,26.732 59.641,26.642 59.58,26.542 59.535,26.432 59.507,26.318 59.498,26.2 59.498,13.75 56.5,13.75 56.5,10.55 47.999,10.55 48.001,45.74 59.498,45.74
232CH_GND on Layer 1 (split plane): 69.49,0.51 61.082,0.51 61.052,0.546 61.002,0.595 61.002,25.448 64.5,25.448 64.618,25.457 64.732,25.485 64.842,25.53 64.942,25.591 65.032,25.668 65.109,25.758 65.17,25.858 65.215,25.968 65.243,26.082 65.252,26.2 65.252,30.875 65.243,30.993 65.215,31.107 65.17,31.217 65.109,31.317 65.032,31.407 64.942,31.484 64.842,31.545 64.732,31.591 64.618,31.618 64.5,31.627 61.002,31.627 61.002,45.74 69.49,45.74
GND on Layer 1 (split plane): 45.443,32.75 45.443,7.95 55.243,7.95 57.443,5.75 57.425,5.732 57.425,0.51 5.044,0.51 5.044,3.184 2.3,5.8 2.3,9.197 2.287,9.21 2.287,11.31 2.97,11.993 2.97,22.27 2.982,22.282 10.42,22.282 10.42,22.275 12.4,22.275 12.4,24.1 12.4,27.782 17.859,27.782 17.859,43.255 17.87,43.271 17.875,43.3 17.875,45.74 25.238,45.74 25.238,42.785 35.762,42.785 35.762,45.74 45.443,45.74

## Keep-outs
Top Layer:
  rectangle: 25.4,42.9 35.762,45.8
  rectangle: 10.95,24.403 11.592,27.7
  rectangle: 47.999,10.55 49.475,14.925
  rectangle: 60.5,16.1 65.8,30.125
  region: 45.44,46.25 45.445,46.245 45.445,7.95 55.245,7.95 57.427,5.768 57.427,0 60.451,0 60.802,0.351 60.802,10.55 48.001,10.55 48.004,10.552 48.004,46.25
  lines w0.15: 14.934,20.171 14.964,20.201 14.964,21.125 14.964,22.975 14.964,23.9 15.505,23.9 16.4,23.9 20.4,23.9 20.4,20.096
Bottom Layer:
  rectangle: 17.869,42.9 35.762,45.8
  rectangle: 13.25,25 20.225,27.7
  rectangle: 10.95,24.403 11.592,27.704
  rectangle: 60.5,16.1 65.8,30.125
  region: 45.44,46.25 45.445,46.245 45.445,7.95 55.245,7.95 57.427,5.768 57.427,0 60.451,0 60.802,0.351 60.802,10.55 48.001,10.55 48.004,10.552 48.004,46.25
Keep-Out Layer:
  rectangle: 56.5,8.85 63.423,13.75
  rectangle: 0,22.55 10.95,28.957
  region: 3,22.3 2.97,22.27 2.97,11.993 2.287,11.31 2.3,11.297 2.3,5.8 5.044,3.184 5.044,0.044 5,0 0,0 0,22.282

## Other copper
Top Layer:
  rectangle net 3.3V: 17.9,17.9 20.399,19.5
  rectangle net 3.3V: 19.1,18.875 20.075,20.502
  rectangle net 3.3V_1: 49.06,42.663 54.034,44.85
  rectangle net NetC9_2: 43.3,32.3 45.1,36.4
  region net 3V3A: 25.8,19.4 25.9,19.5 28.4,19.5 28.5,19.4 28.5,18 28.4,17.9 27,17.9 26.7,17.6 26.7,17.3 25.9,17.3 25.8,17.4
  region net 3.3V: 24.1,17.9 25,17.9 25.2,18.1 25.2,19.4 25.1,19.5 24,19.5
  region net 3.3V: 21.745,17.9 24.2,17.9 24.3,18 24.3,19.4 24.2,19.5 22.1,19.5 21.8,19.2
  region net 3.3V: 21.445,17.9 23.9,17.9 24,18 24,19.4 23.9,19.5 21.8,19.5 21.5,19.2
  region net 3.3V: 11.15,21.05 12.65,21.05 12.65,22.25 12.6,22.3 11.2,22.3 11.15,22.25
  region net NetC2_1: 14.031,19 12.65,20.381 12.65,20.55 11.15,20.55 11.15,19.15 11.25,19.05 13.281,19.05 13.781,18.55 14.031,18.55
  region net NetC6_2: 14.781,18.55 14.781,19 13.466,20.315 13.466,20.469 14.468,20.469 14.534,20.403 14.534,20.171 15.034,19.671 15.031,19.668 15.031,18.55
  region net NetIC1_1: 15.45,23.55 15.5,23.6 17.705,23.6 17.705,23.016 17.671,23.05 15.45,23.05
  region net NetC1_1: 15.45,21.05 15.45,22.55 15.95,22.55 15.95,21.05
  region net NetC1_2: 15.45,20.55 15.45,19.132 15.319,19 15.319,18.55 15.794,18.55 15.794,19.894 15.95,20.05 15.95,20.55
  region net NetIC1_1: 16.725,23.6 16.725,19.757 15.968,19 15.968,18.55 16.444,18.55 17.705,19.812 17.705,23.6
  region net POE_OUT: 14.781,16.45 14.781,15.981 10.69,11.89 10.69,7.94 11.91,7.94 15.82,11.85 16.5,11.85 16.5,14.531 15.031,16 15.031,16.45
  region net GND: 17.7,11.85 21.55,11.85 21.9,12.2 21.9,17 21.6,17.3 17.7,17.3
  region net GND: 14.031,16 14.031,16.45 14.3,16.719 14.3,16.9 13.4,16.9 13.4,16.7 13.531,16.7 13.781,16.45 13.781,16.225
  region net GND: 13.85,18.3 11.4,18.3 11.4,16.7 14.538,16.7 14.582,16.744 14.582,18.3
  region net GND: 15.968,16.45 15.968,16.559 15.77,16.757 15.77,18.3 16.35,18.3 17.35,17.3 21.6,17.3 21.9,17 21.9,15.1
  region net GND: 15.968,16.281 17.7,14.55 21.35,14.55 21.9,15.1 21.9,16.7 16.694,16.7 16.444,16.45 15.968,16.45
  pour cut-out: 5.207,0.5 5.207,3.314 2.03,6.49 0.002,6.49 0,6.492 0,0 5,0 5.044,0.044
Bottom Layer:
  rectangle net NetC9_2: 43.3,34.5 45.1,37.3
  region net NetC9_2: 44.1,36.1 44.1,37.3 40.8,37.3 40.8,36.1
  rectangle net NetC9_2: 40.8,36.3 42.2,39.4
  rectangle net GND: 43.5,38.126 45.275,44.205
  rectangle net 3.3V: 40.3,41.2 42.7,45
  pour cut-out: 5.207,0.5 5.207,3.314 2.03,6.49 0.002,6.49 0,6.492 0,0 5,0 5.044,0.044
Layer 1 (plane layer: these items are gaps in the copper):
  rectangle: 25.238,42.785 35.762,46.199
  rectangle: 10.42,22.275 12.4,24.1
  rectangle: 56.5,9.918 60.52,13.75
  rectangle: 16.4,19.9 20.4,23.9
  rectangle: 44.15,2.051 44.463,2.9
  region: 45.443,46.25 45.443,32.75 45.443,7.95 55.243,7.95 57.443,5.75 57.425,5.732 57.425,0 60.449,0 60.8,0.351 60.8,10.55 55.855,10.55 47.999,10.55 48.001,46.25
  region: 3,22.3 2.97,22.27 2.97,11.993 2.287,11.31 2.287,9.21 2.3,9.197 2.3,5.8 5.044,3.184 5.044,0.5 0,0.5 0,22.282
  region: 17.859,46.282 17.859,27.782 12.4,27.782 12.4,24.018 10.577,22.4 10.577,22.282 0,22.282 0,46.282
  lines w0.15: 17.799,43.3 17.799,46.246 ; 59.8,6.15 59.8,0.55 59.8,0.007 59.804,0.003
  lines w0.254: 10.5,23.85 10.7,23.85
  lines w1.5: 60.25,46.25 60.25,30.875 64.5,30.875 64.5,26.2 60.25,26.2 60.25,0.284 60.52,0.014
Layer 2 (plane layer: these items are gaps in the copper):
  rectangle: 25.238,42.785 35.762,46.199
  rectangle: 10.77,22.388 12.38,23.87
  rectangle: 56.5,9.918 60.52,13.75
  region: 45.443,46.25 45.443,32.75 45.443,7.95 55.243,7.95 57.443,5.75 57.425,5.732 57.425,0 60.449,0 60.8,0.351 60.8,10.55 55.855,10.55 47.999,10.55 48.001,46.25
  region: 12.55,0.95 11.85,0.25 13.25,0.25
  region: 3,22.3 2.97,22.27 2.97,11.993 2.287,11.31 2.287,9.21 2.3,9.197 2.3,5.8 5.044,3.184 5.044,0.5 0,0.5 0,22.282
  region: 59.499,1.035 60.534,0 69.92,0 69.92,46.25 59.501,46.25
  region: 17.812,46.259 17.812,27.77 12.38,27.77 12.38,23.87 10.78,22.27 7.28,22.27 0,22.27 0,46.25 -0.02,46.27
  lines w0.15: 11.85,23.87 20.4,23.87 ; 17.799,43.3 17.799,46.246 ; 17.856,27.9 17.869,27.913 17.869,43.5 ; 20.4,23.9 20.4,19.9 20.467,19.833 25.825,19.833 25.825,19.475 25.85,19.45 25.85,17.35 25.9,17.3 28.811,17.3 28.811,19.251 28.811,19.731 28.075,19.731 28.075,23.85 27.825,24.1 24.2,24.1 24.2,35.2 29.821,35.2 29.901,35.12 29.901,33.3 35.762,33.3 35.762,46.199 ; 36.5,46.249 36.7,46.049
  lines w0.254: 0,22.55 10.45,22.55 ; 11.5,0 12.55,1.05 13.6,0
  lines w0.3: 10.45,22.55 10.6,22.4 12.55,22.4 12.55,20.45 12.55,1.05

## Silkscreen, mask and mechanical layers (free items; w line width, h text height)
Top Overlay:
  region: 40.675,25.65 40.675,24.45 41.275,25.05
  lines w0.15: 17.548,27.148 17.548,27.108 21.797,27.108 ; 20.225,24.401 20.625,24.401 20.776,24.25 21.5,24.25 ; 21.25,24 21.5,24.25 ; 21.255,24.519 21.5,24.273 21.5,24.25 ; 22.552,21.417 22.552,15.148 24.152,13.548 23.848,13.548 ; 28.65,18.299 29.079,17.87 29.1,17.87 29.1,19.45 ; 31.875,35.2 31.925,35.2 32.875,36.15 32.85,36.175 32.475,36.175 ; 32.775,0.475 32.775,0.5 ; 32.775,0.525 32.775,0.5 ; 34.25,0.5 32.775,0.5 ; 39.75,10.45 40.1,10.45 38.1,12.45 38.1,12.9 ; 40.8,4 40.5,4.3 ; 40.8,4.6 40.5,4.3 ; 41.499,3.992 41.799,4.292 ; 41.5,4.6 41.8,4.3 40.5,4.3 ; 57.084,33.754 57.519,33.319 57.519,35.444 ; 38.1,12.9 38.1,16 34.5,16 34.5,14 36.8,14 36.8,12.9 38.1,12.9 ; 40.5,4.3 40.5,4.3 ; 40.5,4.3 40.5,4.3 ; 40.5,4.3 40.5,4.3 ; 10.7,6.5 11.3,7.1 11.9,6.5 10.7,6.5 ; 15.475,26.147 17.488,26.147 17.488,28.775 15.475,28.775 15.475,26.147 ; 21.797,21.452 24.048,21.452 24.048,23.268 21.797,23.268 21.797,21.452 ; 21.8,25.08 24,25.08 24,28.5 21.8,28.5 21.8,25.08 ; 24.152,11.552 26.248,11.552 26.248,13.548 24.152,13.548 24.152,11.552 ; 27.552,15.743 29.381,15.743 29.381,17.848 27.552,17.848 27.552,15.743 ; 40.1,9.3 42.6,9.3 42.6,8.1 43.9,8.1 43.9,11.6 40.1,11.6 40.1,9.3 ; 55.875,35.512 55.944,35.444 59.094,35.444 59.094,42.969 59.1,42.975 56.8,42.975 56.775,42.95 56.775,37 55.875,37 55.875,35.512
  text "FCT-RST" at 38.567,15.276 h0.4
  text "BOOT" at 49.82,13.02 h0.6
  text "5-36V" at 6.05,10.75 h0.8
  text "RP-BOOT" at 49.62,8.72 h0.6
  text "POWER" at 13.75,7.95 h0.6
  text "LINK" at 24.995,7.9 h0.6
  text "TCP" at 30.37,7.87 h0.6
  text "DM" at 40.486,7.865 h0.6 r90
  text "DP" at 42.172,7.865 h0.6 r90
  text "RUN" at 19.42,7.82 h0.6
  text "RESET" at 51.92,7.22 h0.6
  text "GND" at 46.62,7.076 h0.6
  text "NORMAL" at 36.12,4.02 h0.6
  text "AT MODE" at 42.72,4.02 h0.6
Bottom Overlay:
  lines w0.15: 0.73,6.49 1.684,6.49 ; 0.73,10.3 1.684,10.3 ; 1.207,9.824 1.207,10.777 ; 37.3,10.5 36.7,9.9 37.9,9.9 37.3,10.5 ; 37.3,10.5 37.3,10.5
  text "CHG" at 4.74,21.92 h0.8
  text "5~36V" at 2.25,15.1 h0.8 r90
  text "W232N R100" at 59.325,13.875 h2
  text "3V3" at 19.237,3.17 h0.6 r270
  text "DIO" at 21.289,3.17 h0.6 r270
  text "CLK" at 23.241,3.17 h0.6 r270
  text "RST" at 25.246,3.17 h0.6 r270
  text "GND" at 27.37,3.12 h0.6 r270
  text "RX" at 31.22,3.12 h0.6 r270
  text "TX" at 29.22,3.02 h0.6 r270
  text "CHG" at 4.35,0.65 h0.8
Mechanical 7:
  lines w0.15: 0.052,0.052 69.95,0.052 69.95,46.2 0.052,46.2 0.052,0.052
Mechanical 8:
  lines w0.15: 62,23.125 72.92,23.125 ; 66,-2.5 66,4 72.5,4 ; 66,48.75 66,42.25 72.5,42.25
Mechanical 12:
  lines w0.15: -4.748,0.104 0,0.104 0,12.808 -4.748,12.808 -4.748,0.104 ; -3.848,28.927 0,28.927 0,44.73 -3.848,44.73 -3.848,28.927 ; -3.717,13.251 0,13.251 0,22.62 -3.717,22.62 -3.717,13.251 ; 0.052,0.052 69.95,0.052 69.95,46.2 0.052,46.2 0.052,0.052 ; 70.002,7.743 78.918,7.743 78.918,38.453 70.002,38.453 70.002,7.743

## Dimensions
69.95,0.052 to 72.5,4 on Mechanical 8
69.95,0.052 to 66,-2.5 on Mechanical 8
70,0 to 72.92,23.125 on Mechanical 8
0,0 to 3.2,6.45 on Mechanical 8
3.72,18.25 to 0,0 on Mechanical 8
69.95,46.2 to 69.95,0.052 on Mechanical 8
0.052,46.2 to 69.95,46.2 on Mechanical 8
